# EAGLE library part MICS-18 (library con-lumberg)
CONNECTOR
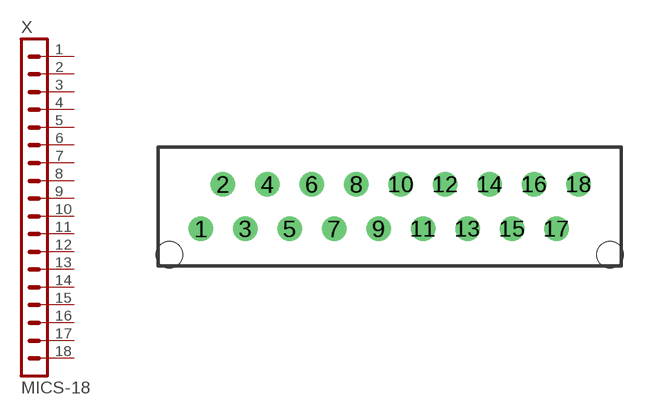
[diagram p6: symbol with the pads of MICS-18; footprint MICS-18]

Designator prefix X

## MICS-18 (OC_FARNELL: unknown; OC_NEWARK: unknown)  [MICS-18]
1  1  pas
2  2  pas
3  3  pas
4  4  pas
5  5  pas
6  6  pas
7  7  pas
8  8  pas
9  9  pas
10  10  pas
11  11  pas
12  12  pas
13  13  pas
14  14  pas
15  15  pas
16  16  pas
17  17  pas
18  18  pas

## Footprint MICS-18 (pad centres in mm)
CONNECTOR
drill 0.85 pad 1.397 round: 1 -10.795,-1.27; 2 -9.525,1.27; 3 -8.255,-1.27; 4 -6.985,1.27; 5 -5.715,-1.27; 6 -4.445,1.27; 7 -3.175,-1.27; 8 -1.905,1.27; 9 -0.635,-1.27; 10 0.635,1.27; 11 1.905,-1.27; 12 3.175,1.27; 13 4.445,-1.27; 14 5.715,1.27; 15 6.985,-1.27; 16 8.255,1.27; 17 9.525,-1.27; 18 10.795,1.27
hole 1.5 at 12.595,-2.75
hole 1.5 at -12.595,-2.75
